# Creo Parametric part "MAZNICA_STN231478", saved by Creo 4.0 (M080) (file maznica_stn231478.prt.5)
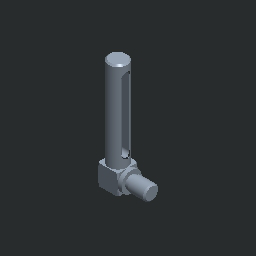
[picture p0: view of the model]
Units: millimeter Kilogram Sec (mmKs); MM, KILOGRAM, SECS
Materials in the file: OCEL_N

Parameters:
  MFG_WP_MATERIAL = "OCEL"
  NAZOV = "MAZNICA_STN231478"
  NORMA = "STN 23 1478"
  PTC_MATERIAL_NAME = "OCEL_N"

Other parameters: HMOTNOST, HUSTOTA, D65

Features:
  1. datum plane "DTM1"
  2. cut
  3. protrusion
  4. cut
  5. chamfer
  6. chamfer
  7. chamfer
  8. protrusion
  9. datum plane "DTM5"
  10. cut
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
Other named items: THRU

Layers: 1, 2, 3, 4, 5, 6, 7, 8, 9, 10, 11, 12, 13, 14, 15, 16, 17, 18, 19, 20, 21, 22, 23, 24, 25, 26, 27, 28, 29, 30, 31, 32

Family table entries: GENERIC, MAZNICA_16X1_5, MAZNICA_STN231478, value(d_val), 2/^, 2/6, 2/H, value(i_val), MAZNICA_20X1_5, MAZNICA_STN231478, !/4, 2/o, 2/D, 2/@, # Pro/TABLE, [] S 92;, [] W 10;, [A] W  3;, [B] W 15;, [C] W 10;, [D] W 10;, [E] W 10;, [F] W 10;, [G] W 10;, [H] W 10;, [I] W 10;

Surfaces: 16 plane, 10 cylinder, 4 cone, 4 ruled, 1 torus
